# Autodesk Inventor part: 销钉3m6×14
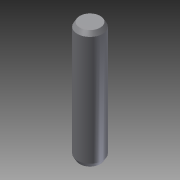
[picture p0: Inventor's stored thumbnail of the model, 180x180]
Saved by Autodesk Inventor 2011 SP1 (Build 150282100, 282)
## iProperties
Created: 2013-12
Part Number: 销钉3m6×14
Document SubType Name: Modeling
Designer: Administrator
Density: 1 g/cm^3
Author: Administrator
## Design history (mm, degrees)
sketch "草图1"
  geometry: C1 r 1.5 at (0, 0); 1 further point
  constraints: 1 centre point, 1 coincident
  dimensions: "d0" = 3 diameter of C1
extrude "拉伸1" new body sketch "草图1" distance "d1" = 14; taper "d2" = 0 deg
sketch "草图2"
  geometry: L1 (-1.5, 14)-(1.5, 14) reference; L2 (-1.5, 0)-(1.5, 0) reference; L3 (-1.5, 0)-(-1.5, 14) reference; L4 (1.5, 0)-(1.5, 14) reference; L5 (1.5, 13.5)-(1.211, 14); L6 (0, -2.8)-(0, 16.8) reference; 1 further point
  constraints: 2 end point, 2 point on line
revolve "旋转1" sketch "草图2" stored, may be unused: angle "d5" = 90 deg
node "工作平面1"
mirror "镜像1"
node "实体1"
node "投影回路1"
other parameters: "d6" = -7
